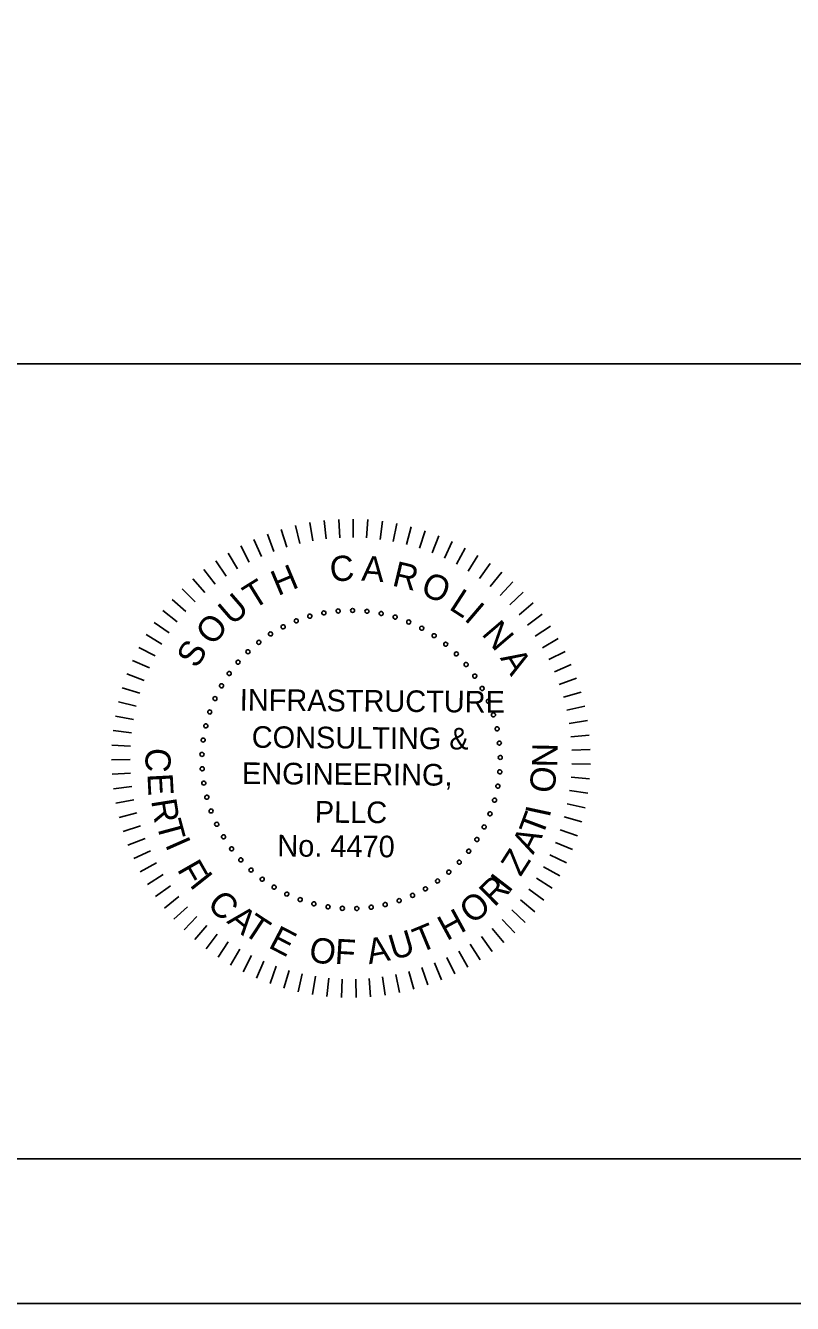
# Model space of a CAD drawing. Extents: x -133.1 to -97, y -1.7 to 20.6.
# Drawn here: x -107.934 to -105.282, y -1.691 to 2.729 of the extents above; entities that cross this region are included whole.
import ezdxf

# ---------------------------------------------------------------- set-up
doc = ezdxf.new("R2010")
doc.units = 0
for name, color, linetype in [('BR_BORDER LINES', 7, 'Continuous'), ('BR_TEXT', 7, 'Continuous'), ('Level 31', 7, 'Continuous')]:
    doc.layers.add(name, color=color, linetype=linetype)

msp = doc.modelspace()

# ---------------------------------------------------------------- linework, layer by layer
at = {"layer": 'BR_BORDER LINES'}
for p, q in [((-110.5071, 1.5591), (-105.1419, 1.5591)), ((-131.3076, -1.191), (-97.6416, -1.191))]:
    msp.add_line(p, q, dxfattribs=at)
at = {"layer": 'BR_TEXT'}
for p, q in [((-106.9012, 1.0172), (-106.894, 0.9539)), ((-106.8509, 1.0213), (-106.8476, 0.9578)), ((-106.8005, 1.0224), (-106.801, 0.9587)), ((-106.75, 1.0204), (-106.7544, 0.9569)), ((-107.0494, 0.9866), (-107.0308, 0.9257)), ((-107.0007, 0.9998), (-106.9858, 0.9379)), ((-106.9512, 1.01), (-106.9401, 0.9473)), ((-106.6998, 1.0153), (-106.7081, 0.9522)), ((-106.65, 1.0071), (-106.6621, 0.9446)), ((-106.6007, 0.996), (-106.6166, 0.9343)), ((-106.5523, 0.9818), (-106.5719, 0.9213)), ((-107.1895, 0.9295), (-107.1601, 0.873)), ((-107.1439, 0.9513), (-107.1181, 0.8932)), ((-107.0972, 0.9704), (-107.0749, 0.9107)), ((-106.5048, 0.9648), (-106.528, 0.9055)), ((-106.4584, 0.9448), (-106.4852, 0.8871)), ((-107.2335, 0.9049), (-107.2008, 0.8503)), ((-106.4133, 0.9221), (-106.4436, 0.8661)), ((-106.3697, 0.8967), (-106.4034, 0.8426)), ((-107.3168, 0.8478), (-107.2776, 0.7976)), ((-107.276, 0.8776), (-107.24, 0.8251)), ((-106.3277, 0.8686), (-106.3646, 0.8167)), ((-107.3557, 0.8156), (-107.3135, 0.7679)), ((-106.2875, 0.8381), (-106.3275, 0.7885)), ((-106.2493, 0.8051), (-106.2922, 0.7581)), ((-107.3925, 0.7811), (-107.3475, 0.736)), ((-106.2131, 0.7699), (-106.2588, 0.7256)), ((-107.4272, 0.7444), (-107.3795, 0.7022)), ((-106.1791, 0.7326), (-106.2275, 0.6911)), ((-107.4895, 0.665), (-107.437, 0.6289)), ((-107.4595, 0.7056), (-107.4094, 0.6664)), ((-106.1475, 0.6932), (-106.1983, 0.6548)), ((-107.5169, 0.6226), (-107.4623, 0.5897)), ((-106.1184, 0.652), (-106.1714, 0.6167)), ((-107.5416, 0.5786), (-107.4852, 0.5491)), ((-106.0918, 0.6091), (-106.1469, 0.5771)), ((-107.5637, 0.5332), (-107.5055, 0.5072)), ((-106.0679, 0.5646), (-106.1248, 0.5361)), ((-107.5829, 0.4865), (-107.5233, 0.4641)), ((-106.0467, 0.5188), (-106.1052, 0.4938)), ((-106.0283, 0.4718), (-106.0883, 0.4504)), ((-107.5992, 0.4387), (-107.5384, 0.42)), ((-106.0129, 0.4237), (-106.0741, 0.406)), ((-107.6126, 0.3901), (-107.5507, 0.3751)), ((-106.0004, 0.3748), (-106.0625, 0.3608)), ((-107.623, 0.3407), (-107.5604, 0.3295)), ((-105.9909, 0.3252), (-106.0538, 0.3151)), ((-107.6304, 0.2907), (-107.5672, 0.2834)), ((-105.9845, 0.2751), (-106.0479, 0.2689)), ((-107.6348, 0.2404), (-107.5712, 0.237)), ((-105.9811, 0.2247), (-106.0448, 0.2224)), ((-107.636, 0.19), (-107.5723, 0.1904)), ((-107.6342, 0.1395), (-107.5706, 0.1438)), ((-105.9809, 0.1743), (-106.0445, 0.1758)), ((-107.6293, 0.0893), (-107.5661, 0.0974)), ((-105.9836, 0.1239), (-106.0471, 0.1292)), ((-107.6213, 0.0394), (-107.5588, 0.0514)), ((-105.9895, 0.0737), (-106.0525, 0.0829)), ((-107.6103, -0.0099), (-107.5487, 0.0059)), ((-105.9984, 0.024), (-106.0607, 0.0371)), ((-107.5964, -0.0584), (-107.5358, -0.0388)), ((-106.0103, -0.025), (-106.0717, -0.0082)), ((-107.5795, -0.106), (-107.5202, -0.0828)), ((-106.0252, -0.0733), (-106.0855, -0.0527)), ((-107.5597, -0.1524), (-107.5019, -0.1256)), ((-106.043, -0.1205), (-106.1019, -0.0963)), ((-107.5371, -0.1976), (-107.4811, -0.1673)), ((-106.0636, -0.1666), (-106.1209, -0.1389)), ((-107.5119, -0.2413), (-107.4578, -0.2077)), ((-106.1131, -0.2545), (-106.1667, -0.22)), ((-106.087, -0.2113), (-106.1426, -0.1802)), ((-107.484, -0.2834), (-107.4321, -0.2465)), ((-106.1418, -0.2961), (-106.1931, -0.2584)), ((-107.4536, -0.3237), (-107.404, -0.2837)), ((-106.173, -0.3358), (-106.2219, -0.2951)), ((-107.4208, -0.362), (-107.3737, -0.3191)), ((-107.3857, -0.3983), (-107.3413, -0.3527)), ((-106.2065, -0.3735), (-106.2529, -0.3299)), ((-107.3485, -0.4324), (-107.307, -0.3841)), ((-106.2801, -0.4426), (-106.3208, -0.3936)), ((-106.2423, -0.4092), (-106.2859, -0.3628)), ((-107.3092, -0.4642), (-107.2708, -0.4135)), ((-107.2681, -0.4935), (-107.2328, -0.4405)), ((-106.32, -0.4736), (-106.3576, -0.4222)), ((-107.2253, -0.5203), (-107.1933, -0.4652)), ((-106.4049, -0.528), (-106.436, -0.4725)), ((-106.3616, -0.5021), (-106.3961, -0.4485)), ((-107.1809, -0.5444), (-107.1523, -0.4875)), ((-107.1352, -0.5657), (-107.1101, -0.5072)), ((-107.0882, -0.5842), (-107.0668, -0.5243)), ((-106.5432, -0.5894), (-106.5637, -0.5291)), ((-106.4959, -0.5718), (-106.52, -0.5128)), ((-106.4498, -0.5513), (-106.4774, -0.4939)), ((-107.0402, -0.5998), (-107.0225, -0.5387)), ((-106.9913, -0.6125), (-106.9773, -0.5504)), ((-106.9418, -0.6221), (-106.9316, -0.5593)), ((-106.8918, -0.6288), (-106.8854, -0.5654)), ((-106.8414, -0.6323), (-106.8389, -0.5687)), ((-106.7909, -0.6328), (-106.7923, -0.5691)), ((-106.7405, -0.6302), (-106.7458, -0.5667)), ((-106.6903, -0.6245), (-106.6995, -0.5615)), ((-106.6406, -0.6158), (-106.6536, -0.5535)), ((-106.5915, -0.6041), (-106.6083, -0.5427))]:
    msp.add_line(p, q, dxfattribs=at)
for centre, start, end in [((-106.8527, 0.7043), 5.0653, 185.0653), ((-106.8029, 0.7062), 359.5268, 179.5268), ((-106.7531, 0.7033), 353.9884, 173.9884), ((-106.9977, 0.6702), 21.6807, 201.6807), ((-106.9977, 0.6702), 201.6807, 21.6807), ((-106.9506, 0.6862), 16.1422, 196.1422), ((-106.9506, 0.6862), 196.1422, 16.1422), ((-106.9021, 0.6977), 10.6038, 190.6038), ((-106.9021, 0.6977), 190.6038, 10.6038), ((-106.8527, 0.7043), 185.0653, 5.0653), ((-106.8029, 0.7062), 179.5268, 359.5268), ((-106.7531, 0.7033), 173.9884, 353.9884), ((-106.7039, 0.6956), 168.4499, 348.4499), ((-106.7039, 0.6956), 348.4499, 168.4499), ((-106.6557, 0.6832), 162.9114, 342.9114), ((-106.6557, 0.6832), 342.9114, 162.9114), ((-106.6088, 0.6662), 157.373, 337.373), ((-106.6088, 0.6662), 337.373, 157.373), ((-107.0864, 0.6248), 32.7576, 212.7576), ((-107.0864, 0.6248), 212.7576, 32.7576), ((-107.0431, 0.6496), 27.2191, 207.2191), ((-107.0431, 0.6496), 207.2191, 27.2191), ((-106.5639, 0.6447), 151.8345, 331.8345), ((-106.5639, 0.6447), 331.8345, 151.8345), ((-106.5212, 0.619), 146.2961, 326.2961), ((-106.5212, 0.619), 326.2961, 146.2961), ((-107.127, 0.5959), 38.2961, 218.2961), ((-107.127, 0.5959), 218.2961, 38.2961), ((-106.4811, 0.5893), 140.7576, 320.7576), ((-106.4811, 0.5893), 320.7576, 140.7576), ((-107.1989, 0.5271), 49.373, 229.373), ((-107.1989, 0.5271), 229.373, 49.373), ((-107.1646, 0.5633), 43.8345, 223.8345), ((-107.1646, 0.5633), 223.8345, 43.8345), ((-106.4442, 0.5559), 135.2191, 315.2191), ((-106.4442, 0.5559), 315.2191, 135.2191), ((-107.2296, 0.4879), 54.9114, 234.9114), ((-107.2296, 0.4879), 234.9114, 54.9114), ((-106.4106, 0.5191), 129.6807, 309.6807), ((-106.4106, 0.5191), 309.6807, 129.6807), ((-107.2563, 0.4458), 60.4499, 240.4499), ((-107.2563, 0.4458), 240.4499, 60.4499), ((-106.3808, 0.4792), 124.1422, 304.1422), ((-106.3808, 0.4792), 304.1422, 124.1422), ((-106.3549, 0.4366), 118.6038, 298.6038), ((-106.3549, 0.4366), 298.6038, 118.6038), ((-107.2788, 0.4014), 65.9884, 245.9884), ((-107.2788, 0.4014), 245.9884, 65.9884), ((-106.3333, 0.3917), 113.0653, 293.0653), ((-106.3333, 0.3917), 293.0653, 113.0653), ((-107.297, 0.3549), 71.5268, 251.5268), ((-107.297, 0.3549), 251.5268, 71.5268), ((-107.3106, 0.307), 77.0653, 257.0653), ((-107.3106, 0.307), 257.0653, 77.0653), ((-106.3161, 0.3449), 107.5268, 287.5268), ((-106.3161, 0.3449), 287.5268, 107.5268), ((-106.3035, 0.2967), 101.9884, 281.9884), ((-106.3035, 0.2967), 281.9884, 101.9884), ((-107.3195, 0.258), 82.6038, 262.6038), ((-107.3195, 0.258), 262.6038, 82.6038), ((-106.2956, 0.2475), 96.4499, 276.4499), ((-106.2956, 0.2475), 276.4499, 96.4499), ((-107.3236, 0.2083), 88.1422, 268.1422), ((-107.3236, 0.2083), 268.1422, 88.1422), ((-106.2925, 0.1977), 90.9114, 270.9114), ((-106.2925, 0.1977), 270.9114, 90.9114), ((-107.3229, 0.1585), 93.6807, 273.6807), ((-107.3229, 0.1585), 273.6807, 93.6807), ((-106.2942, 0.1479), 85.373, 265.373), ((-106.2942, 0.1479), 265.373, 85.373), ((-107.3174, 0.109), 99.2191, 279.2191), ((-107.3174, 0.109), 279.2191, 99.2191), ((-106.3007, 0.0985), 79.8345, 259.8345), ((-106.3007, 0.0985), 259.8345, 79.8345), ((-107.3071, 0.0602), 104.7576, 284.7576), ((-107.3071, 0.0602), 284.7576, 104.7576), ((-106.312, 0.05), 74.2961, 254.2961), ((-106.312, 0.05), 254.2961, 74.2961), ((-107.2922, 0.0126), 110.2961, 290.2961), ((-107.2922, 0.0126), 290.2961, 110.2961), ((-106.3279, 0.0028), 68.7576, 248.7576), ((-106.3279, 0.0028), 248.7576, 68.7576), ((-107.2728, -0.0332), 115.8345, 295.8345), ((-107.2728, -0.0332), 295.8345, 115.8345), ((-106.3483, -0.0427), 63.2191, 243.2191), ((-106.3483, -0.0427), 243.2191, 63.2191), ((-107.249, -0.077), 121.373, 301.373), ((-107.249, -0.077), 301.373, 121.373), ((-106.3729, -0.086), 57.6807, 237.6807), ((-106.3729, -0.086), 237.6807, 57.6807), ((-107.2211, -0.1183), 126.9114, 306.9114), ((-107.2211, -0.1183), 306.9114, 126.9114), ((-106.4016, -0.1267), 52.1422, 232.1422), ((-106.4016, -0.1267), 232.1422, 52.1422), ((-107.1894, -0.1567), 132.4499, 312.4499), ((-107.1894, -0.1567), 312.4499, 132.4499), ((-106.4342, -0.1645), 46.6038, 226.6038), ((-106.4342, -0.1645), 226.6038, 46.6038), ((-107.1541, -0.1919), 137.9884, 317.9884), ((-107.1541, -0.1919), 317.9884, 137.9884), ((-107.1156, -0.2235), 143.5268, 323.5268), ((-107.1156, -0.2235), 323.5268, 143.5268), ((-106.4702, -0.1989), 41.0653, 221.0653), ((-106.4702, -0.1989), 221.0653, 41.0653), ((-107.0742, -0.2512), 149.0653, 329.0653), ((-107.0742, -0.2512), 329.0653, 149.0653), ((-106.5513, -0.2566), 29.9884, 209.9884), ((-106.5513, -0.2566), 209.9884, 29.9884), ((-106.5093, -0.2297), 35.5268, 215.5268), ((-106.5093, -0.2297), 215.5268, 35.5268), ((-107.0303, -0.2749), 154.6038, 334.6038), ((-107.0303, -0.2749), 334.6038, 154.6038), ((-106.9843, -0.2941), 160.1422, 340.1422), ((-106.9843, -0.2941), 340.1422, 160.1422), ((-106.9367, -0.3089), 165.6807, 345.6807), ((-106.9367, -0.3089), 345.6807, 165.6807), ((-106.6899, -0.3114), 13.373, 193.373), ((-106.642, -0.2976), 18.9114, 198.9114), ((-106.642, -0.2976), 198.9114, 18.9114), ((-106.5957, -0.2793), 24.4499, 204.4499), ((-106.5957, -0.2793), 204.4499, 24.4499), ((-106.8879, -0.3189), 171.2191, 351.2191), ((-106.8879, -0.3189), 351.2191, 171.2191), ((-106.8384, -0.3242), 356.7576, 176.7576), ((-106.8384, -0.3242), 176.7576, 356.7576), ((-106.7885, -0.3248), 2.2961, 182.2961), ((-106.7885, -0.3248), 182.2961, 2.2961), ((-106.7389, -0.3205), 7.8345, 187.8345), ((-106.7389, -0.3205), 187.8345, 7.8345), ((-106.6899, -0.3114), 193.373, 13.373)]:
    msp.add_arc(centre, 0.00701, start, end, dxfattribs=at)
at = {"layer": 'Level 31'}
msp.add_lwpolyline([(-133.1409, -1.691), (-97.141, -1.691), (-97.141, 20.309), (-133.1409, 20.309)], close=True, dxfattribs=at)

# ---------------------------------------------------------------- texts
at = {"layer": 'BR_TEXT'}
for s, height, rotation, p in [('C', 0.0872, 4.7281, (-106.8784, 0.8048)), ('A', 0.0872, 355.6981, (-106.7739, 0.8098)), ('H', 0.0872, 22.7882, (-107.0612, 0.7554)), ('R', 0.0872, 346.6681, (-106.6696, 0.7928)), ('T', 0.0872, 31.8182, (-107.1461, 0.7078)), ('O', 0.0872, 337.638, (-106.5719, 0.763)), ('U', 0.0872, 40.8482, (-107.2194, 0.6516)), ('L', 0.0872, 327.108, (-106.4731, 0.7125)), ('I', 0.0872, 319.578, (-106.4205, 0.6747)), ('O', 0.0872, 49.8782, (-107.2864, 0.5806)), ('N', 0.0872, 310.548, (-106.3597, 0.6239)), ('S', 0.0872, 58.9083, (-107.3418, 0.5024)), ('A', 0.0872, 301.5179, (-106.2946, 0.5415)), ('INFRASTRUCTURE', 0.074771, 359.5268, (-107.1932, 0.3599)), ('CONSULTING &', 0.074771, 359.5268, (-107.1519, 0.2313)), ('C', 0.0872, 267.025, (-107.5168, 0.2325)), ('N', 0.0872, 89.2085, (-106.0953, 0.1628)), ('ENGINEERING,', 0.074771, 359.5268, (-107.1855, 0.1059)), ('E', 0.0872, 273.025, (-107.5124, 0.1409)), ('O', 0.0872, 83.2085, (-106.1064, 0.0713)), ('R', 0.0872, 279.025, (-107.4996, 0.0487)), ('PLLC', 0.07477, 359.5268, (-106.9338, -0.0277)), ('T', 0.0872, 69.3954, (-106.1476, -0.0805)), ('I', 0.0872, 77.9093, (-106.1219, -0.013)), ('T', 0.0872, 285.025, (-107.4822, -0.0301)), ('I', 0.0872, 293.7713, (-107.4525, -0.1032)), ('No. 4470', 0.07477, 359.5268, (-107.0633, -0.1446)), ('A', 0.0872, 63.3954, (-106.1784, -0.1408)), ('Z', 0.0872, 57.3954, (-106.2222, -0.2172)), ('F', 0.0872, 299.7713, (-107.4113, -0.1893)), ('I', 0.0872, 308.5268, (-107.3692, -0.2431)), ('R', 0.0872, 44.5268, (-106.3127, -0.3221)), ('I', 0.0872, 52.3339, (-106.2633, -0.2748)), ('C', 0.0872, 314.5268, (-107.3099, -0.3133)), ('O', 0.0872, 38.5268, (-106.3893, -0.3821)), ('A', 0.0872, 320.5268, (-107.2407, -0.3718)), ('T', 0.0872, 326.5268, (-107.1863, -0.4103)), ('H', 0.0872, 28.5268, (-106.4774, -0.4381)), ('E', 0.0872, 332.5268, (-107.0977, -0.4581)), ('T', 0.0872, 22.5268, (-106.5706, -0.4799)), ('O', 0.0872, 350.5268, (-106.9576, -0.507)), ('F', 0.0872, 356.5268, (-106.8661, -0.5161)), ('A', 0.0872, 10.5268, (-106.7462, -0.5177)), ('U', 0.0872, 16.5268, (-106.6623, -0.5042))]:
    msp.add_text(s, height=height, rotation=rotation, dxfattribs=at).set_placement(p)

doc.saveas('drawing.dxf')
